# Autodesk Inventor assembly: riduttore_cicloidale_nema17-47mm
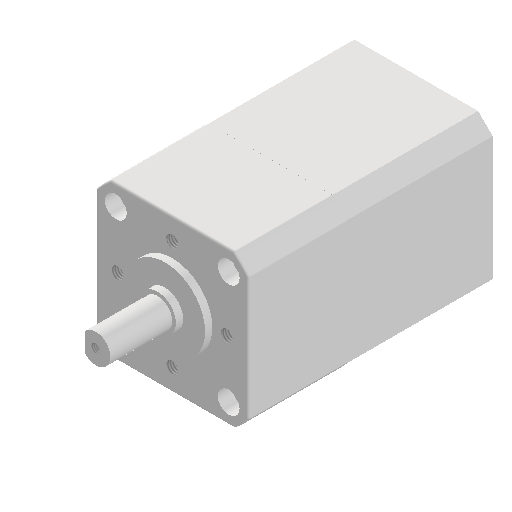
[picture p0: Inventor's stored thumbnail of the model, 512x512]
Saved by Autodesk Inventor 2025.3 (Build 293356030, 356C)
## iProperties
Created: 2026-03
Part Number: riduttore_cicloidale_nema17-47mm
Document SubType Name: Assembly
Designer: R5800u
Author: R5800u
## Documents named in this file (3)
- C:\Users\R5800u\Desktop\Riduttore cicloidale\riduttore_cicloidale_nema17-47mm.iam
- C:\Users\R5800u\Desktop\Riduttore cicloidale\NEMA 17.ipt
- C:\Users\R5800u\Desktop\Riduttore cicloidale\riduttore ciccloidale TS42 15-1.ipt
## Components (2 placed, 2 different names)
1. NEMA 17:1 — Coincidente:1, Coincidente:2, Angolo:1
2. riduttore ciccloidale TS42 15-1:1 — Coincidente:1, Coincidente:2, Angolo:1
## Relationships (3: Mate 2, Angle 1)
- Coincidente:1 [Mate]: NEMA 17:1 ↔ riduttore ciccloidale TS42 15-1:1
- Coincidente:2 [Mate]: NEMA 17:1 ↔ riduttore ciccloidale TS42 15-1:1
- Angolo:1 [Angle]: NEMA 17:1 ↔ riduttore ciccloidale TS42 15-1:1
